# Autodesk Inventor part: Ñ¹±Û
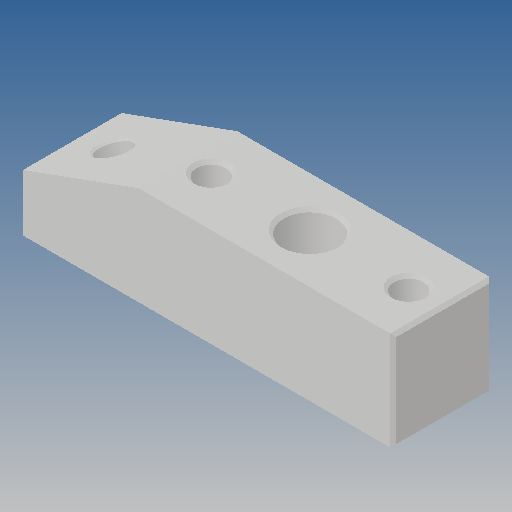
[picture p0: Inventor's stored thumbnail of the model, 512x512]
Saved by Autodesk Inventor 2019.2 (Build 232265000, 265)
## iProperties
Created: 2013-09
Part Number: Ñ¹±Û
Material: Ogólny
Document SubType Name: Modeling
Designer: CADENGINEERING4
Density: 1 g/cm^3
Appearance: Domyślna
Author: CADENGINEERING4
Revision Number: ÈÎºÎ
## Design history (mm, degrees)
feature "µ¹½Ç11"
node "Bryła1"
